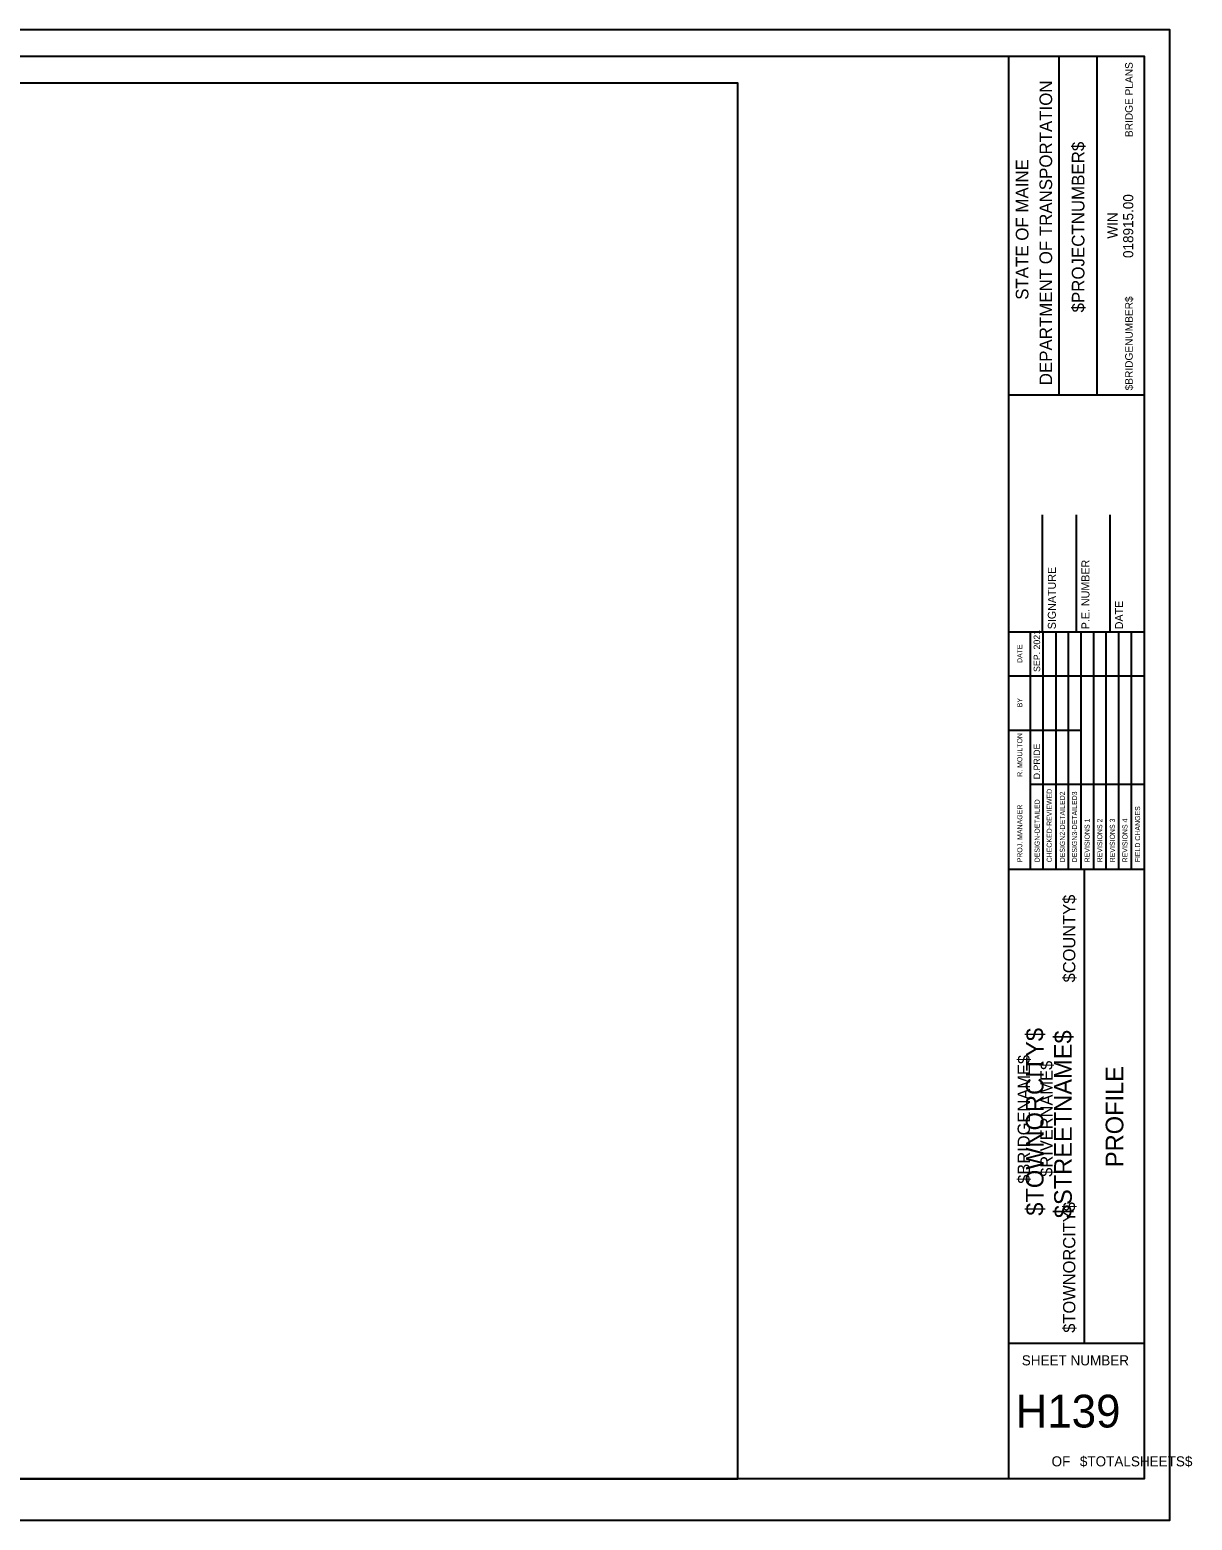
# Model space of a CAD drawing. Extents: x 11796 to 12654, y 9985 to 10535.
# Drawn here: x 12225 to 12654, y 9985 to 10535 of the extents above; entities that cross this region are included whole.
import ezdxf

# ---------------------------------------------------------------- set-up
doc = ezdxf.new("R2010")
doc.units = 0
for name, color, linetype in [('BORDER', 7, 'Continuous'), ('BRIDGE_TITLE', 7, 'Continuous'), ('CLIPS', 7, 'Continuous'), ('HIGHWAY_TITLE', 7, 'Continuous'), ('PLOT BOUNDARY', 7, 'Continuous')]:
    doc.layers.add(name, color=color, linetype=linetype)

msp = doc.modelspace()

# ---------------------------------------------------------------- linework, layer by layer
at = {"layer": 'BORDER'}
for p, q in [((12586.63, 10000), (12586.63, 10525)), ((12605.27, 10399.99), (12605.27, 10524.99)), ((12619.25, 10399.99), (12619.25, 10524.99)), ((12586.63, 10399.97), (12636.63, 10399.97)), ((12599.13, 10312.51), (12599.13, 10355.75)), ((12611.63, 10312.51), (12611.63, 10355.75)), ((12624.13, 10312.51), (12624.13, 10355.75)), ((12586.63, 10312.51), (12636.63, 10312.51)), ((12586.63, 10225.01), (12636.63, 10225.01)), ((12614.58, 10050.01), (12614.58, 10225.01)), ((12586.63, 10050.01), (12636.63, 10050.01))]:
    msp.add_line(p, q, dxfattribs=at)
msp.add_lwpolyline([(11836.63, 10525), (12636.63, 10525), (12636.63, 10000), (11836.63, 10000)], close=True, dxfattribs=at)
for points in [[(12594.7, 10296.26), (12594.7, 10312.51)], [(12599.37, 10225.03), (12599.37, 10312.51)], [(12604.02, 10312.51), (12604.02, 10225.03)], [(12608.68, 10225.03), (12608.68, 10312.51)], [(12613.34, 10225.03), (12613.34, 10312.51)], [(12618, 10225.03), (12618, 10312.51)], [(12622.66, 10225.03), (12622.66, 10312.51)], [(12627.32, 10225.03), (12627.32, 10312.51)], [(12631.98, 10225.03), (12631.98, 10312.51)], [(12594.71, 10225.03), (12594.71, 10308.98)], [(12586.63, 10296.26), (12636.63, 10296.26)], [(12586.63, 10276.26), (12594.71, 10276.26)], [(12594.7, 10276.26), (12613.34, 10276.26)], [(12594.7, 10256.26), (12636.63, 10256.26)]]:
    msp.add_lwpolyline(points, dxfattribs=at)
at = {"layer": 'CLIPS'}
msp.add_lwpolyline([(11836.63, 10000), (12486.63, 10000), (12486.63, 10515), (11836.63, 10515)], close=True, dxfattribs=at)
at = {"layer": 'PLOT BOUNDARY'}
msp.add_lwpolyline([(11796.16, 9984.7), (12646.16, 9984.7), (12646.16, 10534.7), (11796.16, 10534.7)], close=True, dxfattribs=at)

# ---------------------------------------------------------------- texts
at = {"layer": 'BORDER'}
for s, height, p in [('DEPARTMENT OF TRANSPORTATION', 4.6588, (12602.66, 10403.53)), ('$PROJECTNUMBER$', 4.6588, (12614.59, 10430.4)), ('STATE OF MAINE', 4.6588, (12593.91, 10435.06)), ('018915.00', 3.726, (12632.61, 10450.49)), ('WIN', 3.726, (12626.81, 10457.65)), ('SIGNATURE', 2.953, (12604.03, 10313.48)), ('P.E. NUMBER', 2.9528, (12616.43, 10313.48)), ('DATE', 2.953, (12628.83, 10313.48)), ('SEP. 2021', 2.423, (12598.24, 10297.74)), ('DATE', 1.857, (12591.65, 10301.04)), ('BY', 1.857, (12591.65, 10284.69)), ('R. MOULTON', 1.864, (12591.65, 10259.03)), ('D.PRIDE', 2.423, (12598.24, 10258.13)), ('CHECKED-REVIEWED', 1.8637, (12602.53, 10227.46)), ('DESIGN2-DETAILED2', 1.8637, (12607.38, 10227.46)), ('DESIGN3-DETAILED3', 1.8637, (12611.85, 10227.46)), ('PROJ. MANAGER', 1.8637, (12591.65, 10227.46)), ('DESIGN-DETAILED', 1.8637, (12598.06, 10227.46)), ('FIELD CHANGES', 1.8637, (12635.14, 10227.46)), ('REVISIONS 1', 1.8637, (12616.51, 10227.46)), ('REVISIONS 2', 1.8637, (12621.17, 10227.46)), ('REVISIONS 3', 1.8637, (12625.83, 10227.46)), ('REVISIONS 4', 1.8637, (12630.48, 10227.46)), ('PROFILE', 6.521, (12628.95, 10115))]:
    msp.add_text(s, height=height, rotation=90, dxfattribs=at).set_placement(p)
for s, height, p in [('SHEET NUMBER', 3.7264, (12591.46, 10041.83)), ('H139', 12.097, (12589.21, 10018.91)), ('OF', 3.726, (12602.46, 10004.56)), ('$TOTALSHEETS$', 3.7264, (12612.91, 10004.56))]:
    msp.add_text(s, height=height, dxfattribs=at).set_placement(p)
at = {"layer": 'BRIDGE_TITLE'}
for s, height, p in [('BRIDGE PLANS', 2.795, (12632.42, 10495.12)), ('$BRIDGENUMBER$', 2.795, (12632.42, 10401.65)), ('$COUNTY$', 4.536, (12611.23, 10183.17)), ('$BRIDGENAME$', 4.5358, (12594.46, 10108.86)), ('$RIVERNAME$', 4.5358, (12602.85, 10111.43)), ('$TOWNORCITY$', 4.5358, (12611.23, 10053.88))]:
    msp.add_text(s, height=height, rotation=90, dxfattribs=at).set_placement(p)
at = {"layer": 'HIGHWAY_TITLE'}
for s, p in [('$TOWNORCITY$', (12599.49, 10097.06)), ('$STREETNAME$', (12609.93, 10096.16))]:
    msp.add_text(s, height=6.5214, rotation=90, dxfattribs=at).set_placement(p)

doc.saveas('drawing.dxf')
